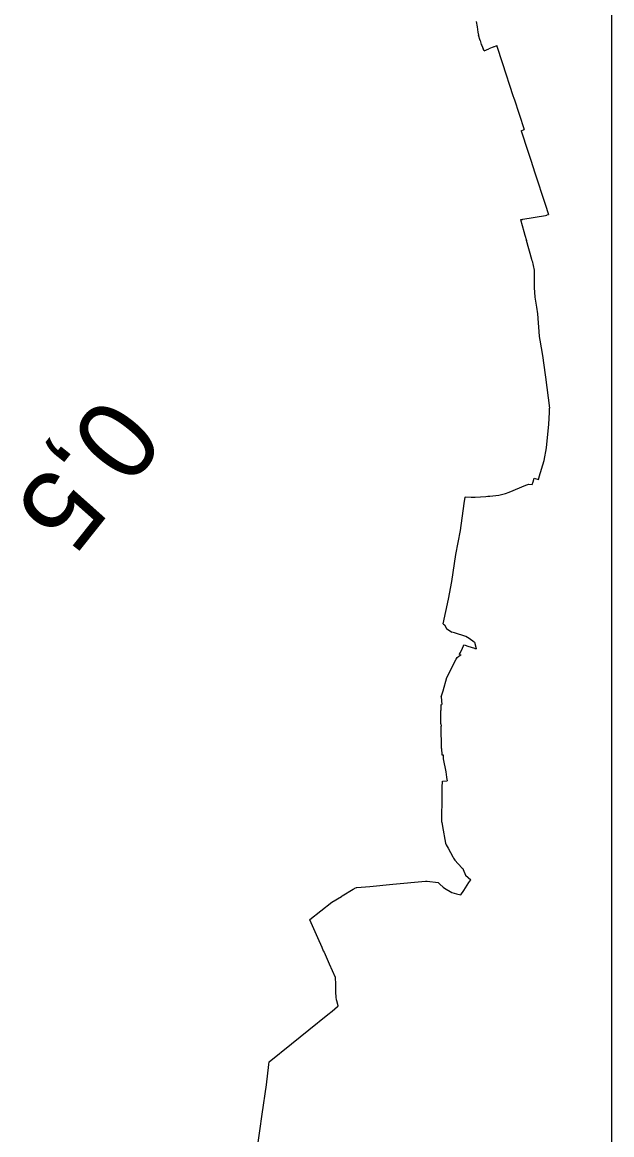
# Model space of a CAD drawing. Extents: x -738519 to -733269, y -1123734 to -1116309.
# Drawn here: x -734380 to -733269, y -1121591 to -1119491 of the extents above; entities that cross this region are included whole.
import ezdxf

# ---------------------------------------------------------------- set-up
doc = ezdxf.new("R2010")
doc.units = 0
for name, color, linetype in [('Implicitní', 7, 'Continuous'), ('Vrstva 13', 7, 'Continuous'), ('Vrstva 7', 7, 'Continuous')]:
    doc.layers.add(name, color=color, linetype=linetype)

msp = doc.modelspace()

# ---------------------------------------------------------------- linework, layer by layer
at = {"layer": 'Implicitní'}
msp.add_line((-733269, -1123733.5), (-733269, -1116308.5), dxfattribs=at)
at = {"layer": 'Vrstva 13'}
for p, q in [((-733524.7, -1119489.6), (-733522.7, -1119500)), ((-733522.7, -1119500), (-733521.1, -1119510.3)), ((-733521.1, -1119510.3), (-733519.8, -1119515.4)), ((-733517.1, -1119525.9), (-733519.8, -1119515.4)), ((-733517.1, -1119525.9), (-733515.7, -1119530.9)), ((-733515.7, -1119530.9), (-733514.8, -1119533.1)), ((-733514.8, -1119533.1), (-733514, -1119535.1)), ((-733514, -1119535.1), (-733513.9, -1119535.2)), ((-733513.9, -1119535.2), (-733511.2, -1119541.5)), ((-733511.1, -1119541.8), (-733511.2, -1119541.5)), ((-733510.3, -1119543.6), (-733511.1, -1119541.8)), ((-733509.7, -1119545.2), (-733510.3, -1119543.6)), ((-733509.7, -1119545.2), (-733500.6, -1119541.6)), ((-733497.6, -1119540.3), (-733500.6, -1119541.6)), ((-733491.1, -1119537.4), (-733497.6, -1119540.3)), ((-733491.1, -1119537.4), (-733485.5, -1119535)), ((-733474.2, -1119570), (-733485.5, -1119535)), ((-733454.5, -1119630.4), (-733474.2, -1119570)), ((-733453.1, -1119635), (-733454.5, -1119630.4)), ((-733452.8, -1119635.9), (-733453.1, -1119635)), ((-733452.8, -1119635.9), (-733434, -1119693.6)), ((-733439.6, -1119695.9), (-733434, -1119693.6)), ((-733439.6, -1119695.9), (-733427.1, -1119734.8)), ((-733427.1, -1119734.8), (-733421.6, -1119751.3)), ((-733421.6, -1119751.3), (-733413.9, -1119775.2)), ((-733413.9, -1119775.2), (-733394.7, -1119834.4)), ((-733394.7, -1119834.4), (-733388.3, -1119854.2)), ((-733439.9, -1119863.7), (-733437.3, -1119863.3)), ((-733437.3, -1119863.3), (-733437.1, -1119863.2)), ((-733437.1, -1119863.2), (-733436.7, -1119863.2)), ((-733436.7, -1119863.2), (-733393.5, -1119856)), ((-733393.5, -1119856), (-733391.1, -1119855.6)), ((-733391.3, -1119854.6), (-733388.3, -1119854.2)), ((-733391.3, -1119854.6), (-733391.1, -1119855.6)), ((-733440.8, -1119863.8), (-733439.9, -1119863.7)), ((-733440.8, -1119863.8), (-733434.8, -1119886.4)), ((-733434.8, -1119886.4), (-733432.9, -1119893.1)), ((-733432.9, -1119893.1), (-733429.9, -1119903.3)), ((-733419.5, -1119938.7), (-733429.9, -1119903.3)), ((-733418.7, -1119941.4), (-733419.5, -1119938.7)), ((-733418.7, -1119941.4), (-733415.4, -1119959.3)), ((-733415.4, -1119959.3), (-733414.9, -1119991.6)), ((-733414.9, -1119991.6), (-733413.7, -1120010.2)), ((-733413.7, -1120010.2), (-733410.9, -1120029.1)), ((-733410.9, -1120029.1), (-733409.1, -1120041.4)), ((-733409.1, -1120041.4), (-733405.7, -1120083.4)), ((-733405.7, -1120083.4), (-733404.9, -1120088.1)), ((-733404.9, -1120088.1), (-733404.4, -1120091.2)), ((-733404.4, -1120091.2), (-733399.4, -1120120.4)), ((-733399.4, -1120120.4), (-733394.4, -1120156.4)), ((-733394.4, -1120156.4), (-733393.8, -1120161.2)), ((-733393.8, -1120161.2), (-733391, -1120180.8)), ((-733391, -1120180.8), (-733386.2, -1120219.5)), ((-733386.5, -1120227.4), (-733386.2, -1120219.5)), ((-733387.3, -1120250), (-733386.5, -1120227.4)), ((-733392.2, -1120294.3), (-733387.3, -1120250)), ((-733396.6, -1120318.2), (-733392.2, -1120294.3)), ((-733405.5, -1120349.2), (-733396.6, -1120318.2)), ((-733462, -1120378), (-733430.7, -1120365)), ((-733430.7, -1120365), (-733425.2, -1120362.7)), ((-733425.2, -1120362.7), (-733418.9, -1120363.6)), ((-733418.9, -1120363.6), (-733417.3, -1120358.7)), ((-733417.3, -1120358.7), (-733415, -1120351.8)), ((-733415, -1120351.8), (-733407, -1120354.4)), ((-733407, -1120354.4), (-733405.6, -1120349.6)), ((-733405.6, -1120349.6), (-733405.5, -1120349.2)), ((-733546.9, -1120399.6), (-733545.1, -1120387.2)), ((-733545.1, -1120386.9), (-733533.9, -1120387.5)), ((-733545.1, -1120386.9), (-733545.1, -1120387.2)), ((-733533.9, -1120387.5), (-733526.6, -1120387.3)), ((-733526.6, -1120387.3), (-733506.2, -1120386.4)), ((-733506.2, -1120386.4), (-733502.7, -1120385.9)), ((-733502.7, -1120385.9), (-733498.7, -1120385.9)), ((-733498.7, -1120385.9), (-733482, -1120383.6)), ((-733482, -1120383.6), (-733469.3, -1120380.7)), ((-733469.3, -1120380.7), (-733462, -1120378)), ((-733553.9, -1120450.3), (-733546.9, -1120399.6)), ((-733562.8, -1120495.8), (-733553.9, -1120450.3)), ((-733570.2, -1120546.8), (-733562.8, -1120495.8)), ((-733576.9, -1120580), (-733570.2, -1120546.8)), ((-733586.9, -1120626.4), (-733576.9, -1120580)), ((-733586.9, -1120626.4), (-733584.2, -1120628.4)), ((-733584.2, -1120628.4), (-733580.4, -1120635.2)), ((-733580.4, -1120635.2), (-733570.4, -1120642)), ((-733565.5, -1120643.6), (-733570.4, -1120642)), ((-733544.1, -1120650.3), (-733565.5, -1120643.6)), ((-733537.9, -1120654.4), (-733544.1, -1120650.3)), ((-733528.2, -1120660.8), (-733537.9, -1120654.4)), ((-733527.5, -1120661.3), (-733528.2, -1120660.8)), ((-733555.6, -1120684), (-733554.2, -1120680.8)), ((-733554.2, -1120680.8), (-733550.5, -1120672.5)), ((-733550.5, -1120672.5), (-733548.6, -1120668)), ((-733548.6, -1120668), (-733547.7, -1120666)), ((-733547.7, -1120666), (-733545.2, -1120666.6)), ((-733545.2, -1120666.6), (-733539.9, -1120668.4)), ((-733539.9, -1120668.4), (-733527.7, -1120672.4)), ((-733527.7, -1120672.4), (-733526.7, -1120672.8)), ((-733527.5, -1120661.3), (-733524.5, -1120672.8)), ((-733526.7, -1120672.8), (-733524.3, -1120673.6)), ((-733524.5, -1120672.8), (-733524.3, -1120673.6)), ((-733579.6, -1120727.9), (-733561.9, -1120693.2)), ((-733561.9, -1120693.2), (-733560, -1120690.2)), ((-733560, -1120690.2), (-733557.4, -1120687.7)), ((-733557.4, -1120687.7), (-733555.2, -1120686.1)), ((-733555.8, -1120684.6), (-733555.6, -1120684)), ((-733555.8, -1120684.6), (-733555.1, -1120684.6)), ((-733555.2, -1120686.1), (-733552.7, -1120685.3)), ((-733555.1, -1120684.6), (-733552.7, -1120685.3)), ((-733586.7, -1120752.7), (-733579.6, -1120727.9)), ((-733590.7, -1120764.2), (-733586.7, -1120752.7)), ((-733590.7, -1120764.2), (-733589, -1120778.4)), ((-733591.4, -1120779.2), (-733589, -1120778.4)), ((-733591.4, -1120779.2), (-733591.2, -1120790)), ((-733590.8, -1120815.4), (-733591.2, -1120790)), ((-733590.8, -1120815.4), (-733590.7, -1120819.8)), ((-733590.1, -1120861.6), (-733590.7, -1120819.8)), ((-733590.1, -1120861.6), (-733589.3, -1120873.6)), ((-733589.3, -1120873.6), (-733586.8, -1120873.7)), ((-733586.8, -1120873.7), (-733586.7, -1120881.5)), ((-733586.7, -1120881.5), (-733581.9, -1120905.5)), ((-733581.9, -1120905.5), (-733581.7, -1120906.4)), ((-733581.7, -1120906.4), (-733581.2, -1120909.9)), ((-733581.2, -1120909.9), (-733580.2, -1120916.7)), ((-733588.4, -1120935.6), (-733588.2, -1120923.6)), ((-733588.2, -1120923.6), (-733579.3, -1120922.9)), ((-733580.2, -1120916.7), (-733579.3, -1120922.9)), ((-733588.7, -1120960.3), (-733588.6, -1120953.4)), ((-733588.6, -1120953.4), (-733588.4, -1120935.6)), ((-733589, -1120989.7), (-733588.7, -1120960.3)), ((-733589.2, -1121000.5), (-733589, -1120989.7)), ((-733589.2, -1121000.5), (-733587.8, -1121008.9)), ((-733587.8, -1121008.9), (-733582.5, -1121040.2)), ((-733582.5, -1121040.2), (-733580.8, -1121043.3)), ((-733580.8, -1121043.3), (-733577.4, -1121049.7)), ((-733577.4, -1121049.7), (-733568.2, -1121066.4)), ((-733568.2, -1121066.4), (-733567, -1121068.6)), ((-733567, -1121068.6), (-733564.9, -1121072.4)), ((-733564.9, -1121072.4), (-733551.2, -1121086.9)), ((-733551.2, -1121086.9), (-733549.9, -1121088.4)), ((-733549.9, -1121088.4), (-733549.2, -1121089.8)), ((-733549.2, -1121089.8), (-733544.6, -1121100.6)), ((-733544.6, -1121100.6), (-733534.6, -1121109.4)), ((-733749.5, -1121124.2), (-733725.1, -1121121.9)), ((-733725.1, -1121121.9), (-733681.6, -1121117.8)), ((-733681.6, -1121117.8), (-733620, -1121112)), ((-733620, -1121112), (-733616.9, -1121112.3)), ((-733616.9, -1121112.3), (-733596.1, -1121114.3)), ((-733596.1, -1121114.3), (-733594.6, -1121115.9)), ((-733594.6, -1121115.9), (-733593, -1121117.8)), ((-733593, -1121117.8), (-733586.8, -1121123.1)), ((-733586.8, -1121123.1), (-733584.3, -1121125.3)), ((-733547.8, -1121129.7), (-733538.1, -1121114.8)), ((-733538.1, -1121114.8), (-733534.6, -1121109.4)), ((-733796.5, -1121152), (-733778.3, -1121140.9)), ((-733778.3, -1121140.9), (-733776.9, -1121140)), ((-733776.9, -1121140), (-733756.6, -1121127.4)), ((-733756.6, -1121127.4), (-733753.6, -1121125.8)), ((-733753.6, -1121125.8), (-733753.1, -1121125.6)), ((-733753.1, -1121125.6), (-733750, -1121124.3)), ((-733750, -1121124.3), (-733749.5, -1121124.2)), ((-733584.3, -1121125.3), (-733570.6, -1121133.3)), ((-733570.6, -1121133.3), (-733561.3, -1121136.3)), ((-733561.3, -1121136.3), (-733553.2, -1121138.1)), ((-733553.2, -1121138.1), (-733547.8, -1121129.7)), ((-733838.1, -1121184.6), (-733796.5, -1121152)), ((-733838.5, -1121184.3), (-733838.1, -1121184.6)), ((-733838.5, -1121184.3), (-733823.6, -1121218.3)), ((-733823.6, -1121218.3), (-733815.5, -1121236.6)), ((-733815.5, -1121236.6), (-733812.6, -1121243.4)), ((-733812.6, -1121243.4), (-733811.2, -1121245.9)), ((-733811.2, -1121245.9), (-733801.4, -1121267.8)), ((-733801.4, -1121267.8), (-733790.2, -1121293)), ((-733790.2, -1121293), (-733789.9, -1121306.9)), ((-733789.9, -1121306.9), (-733789.5, -1121321.2)), ((-733789.5, -1121321.2), (-733789.2, -1121331.4)), ((-733789.2, -1121331.4), (-733788.2, -1121335.2)), ((-733795.7, -1121357.2), (-733785.7, -1121348.8)), ((-733788.2, -1121335.2), (-733787.6, -1121337.3)), ((-733787.6, -1121337.3), (-733785.1, -1121346.5)), ((-733785.7, -1121348.8), (-733784.7, -1121348)), ((-733784.8, -1121347.5), (-733785.1, -1121346.5)), ((-733784.7, -1121348), (-733784.8, -1121347.5)), ((-733839.9, -1121392.8), (-733804, -1121363.9)), ((-733804, -1121363.9), (-733795.7, -1121357.2)), ((-733872.5, -1121418.9), (-733839.9, -1121392.8)), ((-733915, -1121453), (-733872.5, -1121418.9)), ((-733919.7, -1121496.4), (-733915.5, -1121457.8)), ((-733915.5, -1121457.8), (-733915, -1121453)), ((-733927.6, -1121551.6), (-733919.7, -1121496.4)), ((-733932.1, -1121582.9), (-733927.6, -1121551.6)), ((-733935.4, -1121605.4), (-733932.1, -1121582.9))]:
    msp.add_line(p, q, dxfattribs=at)

# ---------------------------------------------------------------- texts
at = {"layer": 'Vrstva 7'}
msp.add_text('0,5', height=150, rotation=231.4794, dxfattribs=at).set_placement((-734226.2, -1120190))

doc.saveas('drawing.dxf')
